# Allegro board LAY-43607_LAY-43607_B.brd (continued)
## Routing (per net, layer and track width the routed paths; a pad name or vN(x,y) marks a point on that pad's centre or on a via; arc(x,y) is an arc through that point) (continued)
D1_MDQ31: length 46.4
  TOP w0.137: v2(80.79,18.2) 80.79,18.64 81.01,18.86 81.62,18.86 81.81,18.67 81.81,18.32 81.67,18.18 81.59,18.18 81.46,18.04 81.46,17.77 81.59,17.63 81.67,17.63 81.81,17.5 81.81,16.86 U16.D7 ; v3(67.83,36.59) 67.42,36.99 U14.L25
  BOTTOM w0.137: v2(80.79,18.2) 80,18.2 78.44,19.75 76.47,19.75 75.82,19.1 75.82,15.79 75.65,15.62 74.9,15.62 74.76,15.76 74.76,16.53 74.9,16.67 75.22,16.67 75.36,16.8 75.36,17.08 75.22,17.22 74.9,17.22 74.76,17.35 74.76,17.63 74.9,17.76 75.22,17.76 75.36,17.9 75.36,18.18 75.22,18.31 74.9,18.31 74.76,18.45 74.76,18.72 74.9,18.86 75.22,18.86 75.36,19 75.36,19.27 75.22,19.41 74.9,19.41 74.76,19.55 74.76,19.89 74.14,20.5 72.34,20.5 72.34,20.5 70.44,20.5 69.93,21.01 69.93,27.33 67.22,30.04 67.22,31.82 66.46,32.59 66.46,35.47 66.62,35.63 66.62,35.97 66.86,36.21 67.22,36.21 67.6,36.59 v3(67.83,36.59)
D1_MDQ32: length 47
  TOP w0.137: U17.G2 56.4,12.91 58.2,12.91 v2(58.2,12.9) ; U14.V24 v3(61.42,37.4)
  BOTTOM w0.137: v3(61.42,37.4) 61.85,36.97 61.85,35.16 61.68,34.99 61.68,33.28 62.06,32.9 62.06,31.26 61.96,31.16 61.96,29.69 62.41,29.23 62.41,29.04 62.12,28.75 62.12,28.56 62.32,28.36 62.51,28.36 62.8,28.65 63,28.65 63.23,28.42 63.23,27.98 63.09,27.84 62.41,27.84 62.27,27.71 62.27,27.43 62.41,27.3 63.09,27.3 63.23,27.16 63.23,26.72 63.44,26.52 63.44,26.32 63.05,25.94 63.05,25.74 63.24,25.55 63.43,25.55 63.71,25.82 64.08,25.82 64.22,25.69 64.22,24.97 64.08,24.84 63.4,24.84 63.26,24.7 63.26,24.42 63.4,24.29 64.08,24.29 64.22,24.15 64.22,23.88 64.08,23.74 63.4,23.74 63.26,23.6 63.26,23.33 63.4,23.19 64.08,23.19 64.22,23.05 64.22,22.53 64.55,22.2 65.25,22.2 65.48,21.97 65.48,20.91 65.63,20.76 66.16,20.76 66.34,20.58 66.34,20.39 66.15,20.2 64.81,20.2 64.58,19.96 64.35,19.96 63.88,20.43 63.65,20.43 63.49,20.27 63.49,20.04 63.96,19.58 63.96,19.35 63.77,19.16 63.12,19.16 62.5,18.54 62.5,17.23 63.23,16.5 63.23,16.27 62.84,15.88 62.55,15.88 62.42,16.02 62.42,16.26 62.17,16.51 61,16.51 60.8,16.31 60.8,15.14 60.57,14.91 60.24,14.91 60,14.67 60,14.26 59.65,13.91 59.18,13.91 59,13.73 59,13.39 58.51,12.9 v2(58.2,12.9)
D1_MDQ33: length 47.1
  TOP w0.137: v3(62.22,35.79) 62.22,35.8 U14.U26 ; U17.F7 v2(60.4,14.51)
  BOTTOM w0.137: v2(60.4,14.51) 60.8,14.11 61.69,14.11 61.85,14.27 61.85,14.75 61.99,14.89 62.26,14.89 62.4,14.75 62.4,14.27 62.62,14.05 63.06,14.05 63.26,14.25 63.26,14.67 63.12,14.8 63.12,15.54 63.67,16.09 64.01,16.09 64.37,16.45 64.37,16.9 64.21,17.06 63.29,17.06 63.13,17.22 63.13,17.45 63.29,17.61 64.21,17.61 64.37,17.77 64.37,18 64.21,18.16 63.29,18.16 63.13,18.32 63.13,18.55 63.29,18.71 64.21,18.71 64.37,18.87 64.37,19.13 64.99,19.75 66.64,19.75 66.88,20 66.88,21.08 66.76,21.21 66.2,21.21 65.92,21.49 65.92,22.01 65.97,22.06 65.97,22.5 65.84,22.64 65.15,22.64 65.01,22.78 65.01,23.05 65.15,23.19 65.84,23.19 65.97,23.33 65.97,23.6 65.84,23.74 65.15,23.74 65.01,23.88 65.01,24.15 65.15,24.29 65.84,24.29 65.97,24.42 65.97,24.7 65.84,24.84 65.15,24.84 65.01,24.97 65.01,25.25 65.15,25.39 65.84,25.39 65.97,25.52 65.97,25.96 65.55,26.39 65.35,26.39 64.87,25.9 64.68,25.9 64.48,26.1 64.48,26.29 64.97,26.77 64.97,26.97 64.77,27.16 64.58,27.16 64.09,26.68 63.9,26.68 63.7,26.87 63.7,27.07 64.19,27.55 64.19,27.74 63.76,28.17 63.76,29.06 63.09,29.74 62.54,29.74 62.4,29.87 62.4,30.77 62.93,31.31 62.93,32.25 62.8,32.38 62.64,32.38 62.5,32.52 62.5,32.93 62.64,33.07 63.2,33.07 63.33,33.2 63.33,33.48 63.2,33.62 62.89,33.62 62.67,33.83 62.67,34.03 62.81,34.16 63.2,34.16 63.33,34.3 63.33,34.69 v3(62.22,35.79)
D1_MDQ34: length 47
  TOP w0.137: v3(59.02,35.79) 59.42,36.19 U14.AA26 ; U17.H3 v2(57.37,12.51)
  BOTTOM w0.137: v3(59.02,35.79) 59.02,35.64 58.53,35.15 58.53,33.71 58.49,33.67 58.49,33.4 57.94,32.86 57.94,27.95 57.84,27.85 57.84,26.87 57.71,26.73 57.53,26.73 57.33,26.93 57.33,27.4 57.19,27.53 57.02,27.53 56.82,27.34 56.82,26.76 56.74,26.68 56.61,26.68 56.43,26.5 56.43,26.27 56.57,26.13 56.98,26.13 57.15,25.97 57.15,25.74 56.98,25.58 56.61,25.58 56.45,25.42 56.45,25.19 56.61,25.03 56.98,25.03 57.15,24.87 57.15,22.46 57.66,21.95 57.66,21.72 57.5,21.56 57.31,21.56 57.15,21.4 57.15,21.09 57.31,20.93 57.5,20.93 57.64,20.79 57.64,20.6 57.5,20.46 57.17,20.46 57.05,20.34 57.05,20.19 57.16,20.07 57.95,20.07 58.15,19.87 58.15,19.42 57.89,19.16 57.29,19.16 57.08,18.95 57.08,18.49 57.28,18.28 58.12,18.28 58.29,18.11 58.29,17.57 58.2,17.48 57.8,17.48 57.21,16.89 57.21,16.74 57.39,16.56 57.58,16.56 57.93,16.91 58.65,16.91 58.83,16.73 58.83,16.28 58.66,16.11 57.94,16.11 57.85,16.19 57.35,16.19 57.19,16.03 57.19,15.18 57.66,14.7 57.66,14.4 57.9,14.17 58.45,14.17 58.59,14.03 58.59,13.63 58.45,13.49 57.78,13.49 57.72,13.42 57.72,13.27 57.58,13.13 57.26,13.13 57.16,13.23 57.16,14.35 56.98,14.53 56.61,14.53 56.44,14.36 56.44,13.27 56.28,13.11 56.05,13.11 55.89,13.27 55.89,13.95 55.73,14.11 55.44,14.11 55.31,13.97 55.31,13 55.55,12.75 57.13,12.75 v2(57.37,12.51)
D1_MDQ35: length 47
  TOP w0.137: U17.H7 59.6,12.91 59.18,12.91 58.92,13.17 58.92,14.94 59.09,15.12 59.41,15.12 59.6,15.32 59.6,15.63 59.5,15.73 59.09,15.73 58.92,15.91 58.92,17 58.05,17.87 58.05,18.06 58.29,18.3 58.29,18.5 58.1,18.69 57.9,18.69 57.49,18.28 57.29,18.28 57.07,18.51 56.89,18.51 55.99,19.41 55.66,19.41 55.49,19.58 55.49,20.23 55.78,20.52 58.97,20.52 59.51,19.97 59.51,19.67 59.4,19.56 59.16,19.56 58.61,20.11 56.25,20.11 56.12,19.97 56.12,19.78 56.75,19.14 58.21,19.14 v2(58.65,18.7) ; U14.W23 61.02,38.59 v3(60.62,38.19)
  BOTTOM w0.137: v3(60.62,38.19) 60.25,37.82 60.25,36.44 60.01,36.2 59.66,36.2 59.43,35.96 59.43,35.63 59.48,35.58 59.48,33.13 59.34,32.99 58.76,32.99 58.38,32.62 58.38,29.31 58.77,28.92 58.77,28.53 58.38,28.14 58.38,27.77 58.29,27.67 58.29,26.57 58,26.29 57.76,26.29 57.59,26.12 57.59,25.04 57.92,24.72 57.92,24.48 57.59,24.15 57.59,23.03 57.59,23.02 57.59,22.97 58.1,22.45 58.1,20.94 58.59,20.46 58.59,19.14 58.65,19.08 v2(58.65,18.7)
D1_MDQ36: length 47
  TOP w0.137: v2(58.71,12.26) 57.97,12.26 57.81,12.11 56.55,12.11 56.15,12.51 U17.H2 ; v3(62.22,37.39) 62.62,37.79 U14.U24
  BOTTOM w0.137: v2(58.71,12.26) 58.95,12.5 59.47,12.5 59.63,12.66 59.63,12.91 59.79,13.07 60.02,13.07 60.18,12.91 60.18,12.66 60.34,12.5 63.71,12.5 64.34,13.13 64.34,14.32 64.71,14.69 65.25,14.69 65.41,14.85 65.41,15.49 65.88,15.96 65.88,16.37 66.02,16.51 67.25,16.51 67.48,16.27 67.48,15.73 67.78,15.43 69.05,15.43 69.36,15.74 69.36,16.34 69.2,16.5 68.07,16.5 67.9,16.67 67.9,16.9 68.05,17.05 69.2,17.05 69.36,17.21 69.36,18.95 67.8,20.51 67.8,20.68 67.77,20.72 67.77,26.58 65.46,28.89 65.46,29.3 65.45,29.31 65.45,30.95 64.12,32.29 64.12,35.53 64.22,35.63 64.22,35.96 64.12,36.06 64.12,36.36 64.2,36.44 64.2,36.75 63.97,36.97 62.64,36.97 v3(62.22,37.39)
D1_MDQ37: length 47
  TOP w0.137: U17.H8 v2(61.2,12.91) ; U14.U25 62.22,36.6 v3(62.22,36.59)
  BOTTOM w0.137: v2(61.2,12.91) 61.6,13.31 62.82,13.31 63.12,13.61 63.42,13.61 63.73,13.92 63.73,14.82 63.57,14.98 63.57,15.36 63.83,15.62 63.84,15.62 63.87,15.65 64.64,15.65 64.81,15.82 64.81,18.95 65.18,19.31 65.58,19.31 65.59,19.31 67.25,19.31 67.48,19.08 67.48,18.38 67.62,18.24 68.55,18.24 68.73,18.43 68.73,18.86 67.36,20.24 67.36,20.5 67.33,20.53 67.33,21.62 67.19,21.76 66.64,21.76 66.5,21.9 66.5,22.17 66.64,22.31 67.19,22.31 67.33,22.45 67.33,22.72 67.19,22.86 66.64,22.86 66.5,23 66.5,23.27 66.64,23.41 67.19,23.41 67.33,23.54 67.33,23.82 67.19,23.96 66.64,23.96 66.5,24.09 66.5,24.37 66.64,24.5 67.19,24.5 67.33,24.64 67.33,24.92 67.19,25.05 66.64,25.05 66.5,25.19 66.5,25.47 66.64,25.6 67.19,25.6 67.33,25.74 67.33,26.4 66.85,26.88 66.65,26.88 66.26,26.49 66.07,26.49 65.88,26.68 65.88,26.88 66.27,27.26 66.27,27.46 66.07,27.65 65.88,27.65 65.49,27.26 65.3,27.26 65.1,27.46 65.1,27.65 65.49,28.04 65.49,28.23 65.29,28.43 65.1,28.43 64.71,28.04 64.52,28.04 64.32,28.24 64.32,28.43 64.71,28.82 64.71,29.01 64.23,29.49 64.23,30.08 64.1,30.22 63.51,30.22 63.37,30.36 63.37,30.64 63.51,30.77 64.06,30.77 64.23,30.95 64.23,31.22 63.68,31.77 63.68,35.04 63.43,35.29 63.43,35.97 63.21,36.2 62.62,36.2 v3(62.22,36.59)
D1_MDQ38: length 47
  TOP w0.137: v3(60.62,37.4) U14.W24 ; U17.J3 57.99,11.71 v2(58.08,11.79)
  BOTTOM w0.137: v2(58.08,11.79) 57.83,11.55 57.83,10.58 58.03,10.38 58.46,10.38 59.17,11.09 59.43,11.09 59.66,11.32 59.66,11.69 60.08,12.11 62.71,12.11 62.95,11.87 63.75,11.87 64.49,12.61 65.57,12.61 65.85,12.9 65.85,14.7 66.07,14.91 68.11,14.91 68.27,15.07 69.43,15.07 69.61,15.25 69.61,19.41 68.24,20.78 68.24,20.87 68.21,20.9 68.21,26.76 65.9,29.07 65.9,29.48 65.89,29.49 65.89,31.14 64.6,32.43 64.6,37.25 64.09,37.77 61,37.77 v3(60.62,37.4)
D1_MDQ39: length 47
  TOP w0.137: v2(57.56,17.88) 58.56,16.88 58.56,13.15 U17.J7 ; v3(59.82,36.59) 60.22,36.99 U14.Y25
  BOTTOM w0.137: v3(59.82,36.59) 59.62,36.59 59.24,36.21 58.8,36.21 58.66,36.08 58.66,35.96 58.65,35.95 58.65,35.8 58.62,35.77 58.62,35.63 58.39,35.4 58.26,35.4 58.13,35.26 58.13,34.08 57.81,33.77 57.81,33.32 57.49,32.99 57.49,28.63 55.99,27.13 55.99,24.71 56.36,24.34 56.54,24.34 56.7,24.18 56.7,23.95 56.54,23.79 56.36,23.79 56.2,23.63 56.2,23.4 56.36,23.24 56.54,23.24 56.7,23.08 56.7,22.86 56.54,22.69 56.36,22.69 56.2,22.53 56.2,22.31 56.36,22.15 56.54,22.15 56.7,21.99 56.7,21.76 56.54,21.6 56.36,21.6 56.2,21.44 56.2,21.21 56.36,21.05 56.54,21.05 56.7,20.89 56.7,20.66 56.54,20.5 55.79,20.5 55.65,20.36 55.65,20.16 55.86,19.95 56.54,19.95 56.7,19.79 56.7,19.56 56.54,19.4 55.79,19.4 55.65,19.27 55.65,19.06 55.86,18.85 56.54,18.85 56.7,18.69 56.7,18.09 56.82,17.97 56.82,17.44 56.62,17.24 56.11,17.24 56,17.13 56,15.94 55.77,15.71 54.58,15.71 54.58,15.71 54.51,15.71 54.35,15.54 53.44,15.54 53.24,15.34 53.24,15.06 53.39,14.91 55.77,14.91 55.77,14.9 56.6,14.9 56.86,15.16 56.86,17 57.24,17.38 57.24,17.56 v2(57.56,17.88)
D1_MDQ40: length 46.9
  TOP w0.137: v2(59.95,19.22) 59.95,20.22 59.21,20.96 55.6,20.96 55.05,20.41 55.05,19.3 55.2,19.14 55.77,19.14 U17.A3 ; U14.AB24 58.63,37.8 v3(59.02,38.19)
  L4_INT_2 w0.107: v3(59.02,38.19) 58.67,37.84 58,37.84 57.78,37.62 57.78,37.24 57.52,36.97 57.26,36.97 57.01,36.72 57.01,35.96 57.01,35.96 57.01,35.41 56.88,35.29 56.47,35.29 56.31,35.13 56.31,34.98 56.43,34.86 56.99,34.86 57.13,34.72 57.13,34.57 56.99,34.43 56.62,34.43 56.5,34.31 56.5,34.13 56.62,34.01 56.83,34.01 56.94,33.9 56.94,33.26 56.32,32.63 56.32,32.48 56.43,32.38 57.02,32.38 57.07,32.33 57.07,32 57.02,31.95 56.39,31.95 56.27,31.82 56.27,25.1 55.67,24.51 55.67,24.33 56.05,23.96 56.05,23.79 55.92,23.66 55.73,23.66 55.37,24.03 55.19,24.03 55.03,23.86 55.03,21.45 55.19,21.29 55.57,21.29 55.69,21.41 55.69,22.91 55.8,23.02 55.95,23.02 56.12,22.85 56.12,21.4 56.24,21.27 56.42,21.27 56.55,21.4 56.55,22.53 56.67,22.65 56.85,22.65 56.97,22.53 56.97,21.41 57.1,21.29 57.4,21.29 57.53,21.41 57.53,21.82 57.68,21.97 57.84,21.97 57.95,21.86 57.95,21.41 58.08,21.29 58.42,21.29 59.4,20.31 59.4,19.39 59.57,19.22 v2(59.95,19.22)
D1_MDQ41: length 46.9
  TOP w0.137: U17.B8 60.42,16.93 60.42,16.92 v2(60.4,16.91) ; v3(58.22,36.59) 58.62,36.99 U14.AB25
  L4_INT_2 w0.107: v2(60.4,16.91) 59.83,16.91 59.04,16.12 57.76,16.12 55.53,13.9 55.53,12.59 55.76,12.36 56.12,12.36 56.37,12.62 56.37,13.42 57.9,14.95 58.53,14.95 60.07,16.49 61.04,16.49 61.21,16.49 61.62,16.9 61.62,18.65 62.06,19.09 62.06,19.56 61.93,19.69 61.39,19.69 61.27,19.81 61.27,19.99 61.39,20.11 61.93,20.11 62.06,20.24 62.06,20.41 61.93,20.54 61.39,20.54 61.27,20.66 61.27,20.84 61.39,20.97 61.93,20.97 62.06,21.09 62.06,21.27 61.93,21.39 61.39,21.39 61.27,21.52 61.27,21.7 61.39,21.82 61.93,21.82 62.06,21.95 62.06,23.82 60.28,25.6 60.28,30.05 60.28,30.05 60.28,30.2 59.5,30.98 59.5,31.33 59.37,31.46 58.54,31.46 58.42,31.58 58.42,31.76 58.54,31.88 59.37,31.88 59.5,32.01 59.5,32.19 59.37,32.31 58.54,32.31 58.42,32.44 58.42,32.61 58.54,32.74 59.37,32.74 59.5,32.86 59.5,33.92 59.39,34.03 59.18,34.03 59.07,34.14 59.07,34.35 59.18,34.46 59.39,34.46 59.5,34.56 59.5,35.12 59.18,35.44 58.88,35.44 58.61,35.7 58.61,36.21 v3(58.22,36.59)
D1_MDQ42: length 46.9
  TOP w0.137: U14.AE25 56.22,36.99 v3(56.62,36.59) ; v2(58.1,16.51) 58.1,15.97 57.55,15.42 57.35,15.42 57.22,15.56 57.22,16.17 57.54,16.49 57.54,16.78 57.4,16.91 57.21,16.91 U17.C3
  L4_INT_2 w0.107: v2(58.1,16.51) 59.02,16.51 59.28,16.77 59.28,16.94 58.85,17.38 58.85,17.54 58.99,17.69 59.14,17.69 59.58,17.25 59.89,17.25 60.02,17.38 60.02,17.83 59.93,17.92 59.42,17.92 59.29,18.04 59.29,18.22 59.42,18.34 59.8,18.34 59.93,18.47 59.93,18.7 59.7,18.94 59.27,18.94 58.99,19.22 58.99,20.03 58.14,20.88 57.02,20.88 56.16,20.02 56.16,19.34 55.99,19.17 55.84,19.17 55.76,19.25 55.76,19.82 55.61,19.96 55.46,19.96 55.33,19.83 55.33,19.26 55.23,19.17 55.05,19.17 54.95,19.27 54.95,19.63 54.51,20.07 54.51,20.22 54.62,20.33 55.94,20.33 56.04,20.43 56.04,20.63 55.92,20.75 54.74,20.75 54.62,20.88 54.62,24.21 55.08,24.67 55.25,24.67 55.86,25.28 55.86,29.23 55.76,29.33 55.53,29.33 55.43,29.42 55.43,29.57 55.51,29.65 55.76,29.65 55.86,29.74 55.86,29.87 55.76,29.97 55.51,29.97 55.43,30.05 55.43,30.21 55.51,30.29 55.76,30.29 55.86,30.38 55.86,30.51 55.76,30.61 55.51,30.61 55.43,30.69 55.43,30.85 55.51,30.93 55.76,30.93 55.86,31.02 55.86,31.15 55.76,31.25 55.51,31.25 55.43,31.33 55.43,31.49 55.51,31.57 55.76,31.57 55.86,31.66 55.86,31.79 55.76,31.89 55.63,31.89 55.53,31.99 55.53,32.09 55.65,32.21 55.76,32.21 55.86,32.3 55.86,32.43 55.72,32.57 55.72,32.72 56.31,33.32 56.31,34.01 56.12,34.21 55.46,34.21 55.15,34.52 55.15,34.65 55.3,34.8 55.3,34.94 55.2,35.03 55.07,35.03 54.92,34.88 54.79,34.88 54.62,35.04 54.62,35.29 54.73,35.4 56.02,35.4 56.18,35.56 56.18,36.15 v3(56.62,36.59)
D1_MDQ43: length 46.7
  TOP w0.137: U17.C7 59.53,16.98 59.53,18.57 58.45,19.64 v2(57.63,19.64) ; U14.AF25 55.43,37 v3(55.82,37.39)
  L4_INT_2 w0.107: v3(55.82,37.39) 54.89,37.39 54.51,37.01 53.67,37.01 53.23,37.45 51.57,37.45 51.25,37.13 51.25,34.01 51.57,33.69 52.8,33.69 53.02,33.91 53.52,33.91 53.81,33.62 53.81,33.32 54.1,33.03 54.1,32.65 54.1,32.65 54.1,25.46 52.85,24.21 52.85,17.05 52.59,16.79 52.59,15.57 52.7,15.46 52.78,15.38 52.78,14.81 52.55,14.58 52.55,14.03 52.9,13.68 53.41,13.68 53.66,13.93 53.66,14.49 53.66,14.49 53.66,16.23 53.95,16.52 54.99,16.52 55.22,16.75 55.22,17.1 55.43,17.31 56.55,17.31 56.78,17.55 56.78,17.73 57.63,18.57 v2(57.63,19.64)
D1_MDQ44: length 46.8
  TOP w0.137: v3(59.82,37.39) 59.82,37.4 U14.Y24 ; v2(55.6,16.91) U17.C2
  L4_INT_2 w0.107: v3(59.82,37.39) 60.21,37.01 60.21,33.21 61.12,32.3 61.12,25.95 62.88,24.19 62.88,16.58 62.48,16.18 62.48,12.29 62.34,12.15 59.98,12.15 59.7,11.87 59.1,11.87 58.88,11.65 58.88,11.29 58.5,10.91 57.34,10.91 56.96,11.29 56.6,11.29 56.38,11.51 56.38,11.87 56.16,12.09 54.25,12.09 53.67,11.51 52.86,11.51 52.65,11.72 52.65,11.99 52.79,12.13 53.48,12.13 54.42,13.06 54.42,13.07 54.64,13.29 54.96,13.29 55.2,13.54 55.2,14.69 55.44,14.92 55.76,14.92 55.98,15.15 55.98,16.52 v2(55.6,16.91)
D1_MDQ45: length 46.8
  TOP w0.137: U14.AA25 59.42,37 v3(59.02,37.39) ; U17.C8 v2(60.4,16.11)
  L4_INT_2 w0.107: v2(60.4,16.11) 60.67,15.84 60.67,15.8 60.78,15.68 60.78,15.05 60.62,14.89 59.06,14.89 57.52,13.35 56.93,13.35 56.68,13.1 56.68,11.98 57.45,11.21 58.22,11.21 58.51,11.5 58.51,11.92 58.29,12.14 58.29,12.39 58.55,12.65 58.94,12.65 59.33,12.26 59.54,12.26 59.73,12.45 59.73,12.6 59.03,13.3 59.03,13.75 59.37,14.09 60.36,14.09 60.78,13.67 60.78,12.63 60.89,12.52 61.44,12.52 61.58,12.67 61.58,14.23 61.71,14.36 62.14,14.36 62.26,14.48 62.26,14.66 62.14,14.78 61.71,14.78 61.58,14.91 61.58,16.23 61.84,16.49 62.13,16.49 62.47,16.83 62.47,24.02 60.69,25.8 60.69,31.84 59.99,32.55 59.99,35.09 59.4,35.68 59.4,37.02 v3(59.02,37.39)
D1_MDQ46: length 46.7
  TOP w0.137: U14.AD25 57.03,37 v3(57.42,37.39) ; U17.D3 v2(56.4,16.11)
  L4_INT_2 w0.107: v3(57.42,37.39) 57.37,37.39 56.95,36.98 55.11,36.98 54.87,36.75 53.58,36.75 53.28,37.04 51.93,37.04 51.66,36.77 51.66,34.53 51.9,34.29 54.06,34.29 54.62,33.73 54.62,33.32 54.62,33.32 54.62,32.18 54.61,32.17 54.61,28.66 54.74,28.54 54.9,28.54 55.03,28.41 55.03,28.23 54.9,28.11 54.74,28.11 54.61,27.98 54.61,27.81 54.74,27.68 54.9,27.68 55.03,27.56 55.03,27.38 54.9,27.26 54.74,27.26 54.61,27.13 54.61,26.95 54.74,26.83 54.9,26.83 55.03,26.7 55.03,26.53 54.9,26.4 54.74,26.4 54.61,26.28 54.61,26.04 54.74,25.92 54.91,25.92 55.03,25.79 55.03,25.62 54.91,25.49 54.74,25.49 53.26,24.02 53.26,16.97 53.4,16.84 53.68,16.84 53.78,16.94 54.29,16.94 54.68,17.32 54.96,17.32 55.18,17.55 55.18,17.87 55.44,18.12 56.52,18.12 56.98,18.58 56.98,19.67 57.36,20.06 57.8,20.06 58.1,19.75 58.1,19.21 58.25,19.06 58.25,18.82 58.13,18.7 57.98,18.7 57.85,18.57 57.85,18.4 57.98,18.27 58.13,18.27 58.25,18.15 58.25,17.2 57.8,16.75 57.63,16.75 57.19,17.19 57.02,17.19 56.9,17.07 56.9,16.88 57.33,16.45 57.33,16.22 56.99,15.88 56.63,15.88 v2(56.4,16.11)
D1_MDQ47: length 46.7
  TOP w0.137: U17.D7 59.24,16.47 59.24,17.42 v2(58.69,17.97) ; v3(55.82,35.8) U14.AE26
  L4_INT_2 w0.107: v2(58.69,17.97) 59.03,18.32 59.03,18.86 58.51,19.38 58.51,19.92 57.97,20.47 57.19,20.47 56.57,19.85 56.57,19.19 56.27,18.89 55.44,18.89 55.22,18.67 55.22,18.21 55.1,18.09 54.64,18.09 54.27,17.72 53.96,17.72 53.67,18 53.67,18.39 53.8,18.52 54.16,18.52 54.28,18.63 54.28,18.81 54.14,18.94 53.8,18.94 53.67,19.07 53.67,19.25 53.8,19.37 53.96,19.37 54.08,19.5 54.08,19.67 53.96,19.8 53.8,19.8 53.67,19.92 53.67,20.29 53.8,20.42 53.97,20.42 54.1,20.54 54.1,20.72 53.97,20.85 53.8,20.85 53.67,20.97 53.67,21.15 53.8,21.27 53.97,21.27 54.1,21.4 54.1,21.57 53.97,21.7 53.8,21.7 53.67,21.82 53.67,22 53.8,22.13 53.97,22.13 54.1,22.25 54.1,22.43 53.97,22.55 53.8,22.55 53.67,22.68 53.67,22.85 53.8,22.98 53.97,22.98 54.1,23.1 54.1,23.28 53.97,23.41 53.8,23.41 53.67,23.53 53.67,23.85 54.91,25.08 55.08,25.08 55.45,25.45 55.45,25.96 55.44,25.97 55.44,28.83 55.02,29.25 55.02,32 55.03,32 55.03,32.18 55.25,32.4 55.25,33.98 54.65,34.59 53.1,34.59 52.99,34.7 52.27,34.7 52.11,34.86 52.11,35.35 52.24,35.48 54.2,35.48 54.32,35.59 54.32,35.77 54.19,35.9 52.24,35.9 52.11,36.03 52.11,36.4 52.34,36.63 53.38,36.63 53.65,36.36 55.25,36.36 v3(55.82,35.8)
D1_MDQ48: length 47.6
  TOP w0.137: v3(59.02,38.99) 59.42,39.39 U14.AA22 ; U18.G2 44.92,13.71 44.92,14.27 45.16,14.51 45.71,14.51 45.91,14.71 47.67,14.71 v2(48.02,14.36)
  BOTTOM w0.137: v3(59.02,38.99) 58.62,38.59 58.62,37.23 58.36,36.97 58.07,36.97 57.8,36.69 57.8,36.44 57.57,36.21 57.26,36.21 57.02,35.97 57.02,35.63 56.36,34.97 56.36,32.28 56.26,32.18 56.26,29.03 55,27.77 55,24.15 54.38,23.53 54.38,23.3 55,22.68 55,22.37 54.87,22.24 54.67,22.24 53.99,22.91 53.76,22.91 53.6,22.75 53.6,22.52 54.25,21.87 54.25,21.62 54.09,21.46 53.89,21.46 53.22,22.13 52.99,22.13 52.83,21.97 52.83,21.75 53.48,21.1 53.48,20.84 53.32,20.68 53.11,20.68 52.44,21.36 52.21,21.36 51.06,20.21 51.06,17.84 51.23,17.68 51.62,17.68 51.78,17.52 51.78,17.29 51.62,17.13 51.23,17.13 51.06,16.97 51.06,16.74 51.23,16.58 51.62,16.58 51.78,16.42 51.78,16.19 51.62,16.03 51.23,16.03 51.06,15.87 51.06,14.54 50.63,14.11 50.26,14.11 50.12,13.97 50.12,12.67 49.98,12.53 49.45,12.53 49.32,12.66 49.32,13.07 49.09,13.31 48.66,13.31 48.3,13.66 48.3,14.08 v2(48.02,14.36)
D1_MDQ49: length 47.6
  TOP w0.137: U18.F7 v2(48.92,14.51) ; v3(58.22,38.19) 58.62,38.59 U14.AB23
  BOTTOM w0.137: v3(58.22,38.19) 58.22,37.96 57.82,37.56 57.82,37.27 57.58,37.02 57.31,37.02 57.01,36.72 57.01,36.45 56.78,36.22 56.48,36.22 56.23,35.96 56.23,35.67 55.98,35.42 55.44,35.42 55.22,35.2 55.22,34.46 55.08,34.33 54.79,34.33 54.66,34.19 54.66,33.92 54.82,33.76 55.23,33.76 55.39,33.59 55.39,33.37 55.23,33.21 54.74,33.21 54.58,33.05 54.58,32.82 54.75,32.66 55.62,32.66 55.77,32.51 55.77,32.28 55.6,32.11 54.82,32.11 54.66,31.95 54.66,31.72 54.82,31.56 55.62,31.56 55.77,31.41 55.77,31.18 55.6,31.01 54.91,31.01 54.74,30.84 54.74,30.11 54.97,29.88 55.68,29.88 55.82,29.74 55.82,29.47 55.68,29.33 55.36,29.33 55.22,29.19 55.22,28.62 54.39,27.79 54.39,26.15 53.75,25.52 53.75,25.32 54.41,24.66 54.41,24.47 54.22,24.27 54.03,24.27 53.26,25.04 53.07,25.04 52.87,24.84 52.87,24.65 53.73,23.79 53.73,23.6 53.54,23.4 53.34,23.4 52.49,24.26 52.29,24.26 52.1,24.07 52.1,23.87 52.95,23.02 52.95,22.82 52.76,22.63 52.57,22.63 51.71,23.48 51.52,23.48 51.32,23.29 51.32,23.1 52.18,22.24 52.18,22.05 51.98,21.85 51.79,21.85 51.04,22.61 50.84,22.61 50.62,22.38 50.62,22.05 50.49,21.92 49.86,21.92 49.7,21.75 49.7,21.5 49.83,21.37 50.49,21.37 50.62,21.23 50.62,19.69 50.08,19.15 49.78,19.15 49.24,18.61 49.24,15.49 48.92,15.17 v2(48.92,14.51)
D1_MDQ50: length 47.7
  TOP w0.137: v3(58.22,39.8) 57.82,39.4 U14.AC22 ; U18.H3 v2(44.92,12.91)
  BOTTOM w0.137: v2(44.92,12.91) 42.54,12.91 42.3,13.15 42.3,13.51 41.79,14.02 41.79,14.66 41.95,14.82 42.37,14.82 42.53,14.98 42.53,15.21 42.37,15.37 41.95,15.37 41.79,15.53 41.79,25.71 43.62,27.53 43.62,29.02 43.17,29.47 42.9,29.47 42.76,29.61 42.76,30.12 42.9,30.26 43.49,30.26 44.23,31 44.23,32.19 44.56,32.53 44.56,32.76 44.04,33.28 44.04,33.51 44.2,33.67 44.43,33.67 44.95,33.14 45.18,33.14 45.34,33.3 45.34,33.53 44.82,34.05 44.82,34.28 44.98,34.44 45.2,34.44 45.73,33.92 45.95,33.92 46.5,34.47 46.5,34.99 46.75,35.24 47.27,35.24 51.83,39.8 54.46,39.8 54.86,40.19 56.79,40.19 57.19,39.8 v3(58.22,39.8)
D1_MDQ51: length 47.7
  TOP w0.137: U14.AB22 58.62,39.39 v3(58.22,38.99) ; U18.H7 v2(48.12,12.91)
  BOTTOM w0.137: v3(58.22,38.99) 57.85,38.62 57.85,38.09 57.58,37.82 57.32,37.82 57.02,37.52 57.02,37.23 56.79,37 56.4,37 56.25,36.85 56.25,36.46 55.99,36.2 55.37,36.2 55.21,36.36 55.21,36.49 55.08,36.63 54.8,36.63 54.66,36.49 54.66,36.33 54.53,36.2 54.18,36.2 53.83,35.85 53.83,34.83 53.76,34.77 53.76,33.18 53.91,33.03 53.91,32.48 53.75,32.32 53.5,32.32 53.34,32.16 53.34,31.94 53.5,31.77 53.75,31.77 53.91,31.61 53.91,31.35 53.77,31.21 53.5,31.21 53.36,31.08 53.36,30.8 53.5,30.66 54.16,30.66 54.29,30.53 54.29,30.25 54.16,30.12 53.47,30.12 53.34,29.98 53.34,29.7 53.47,29.57 54.57,29.57 54.71,29.43 54.71,29.16 54.57,29.02 53.47,29.02 53.34,28.88 53.34,28.61 53.47,28.47 53.77,28.47 53.91,28.33 53.91,27.68 53.33,27.11 53.33,26.91 53.67,26.58 53.67,26.35 53.06,25.74 52.84,25.74 52.53,26.05 52.3,26.05 52.14,25.88 52.14,25.66 52.45,25.35 52.45,25.13 52.29,24.96 52.06,24.96 51.76,25.27 51.53,25.27 51.37,25.11 51.37,24.88 51.67,24.58 51.67,24.35 51.51,24.19 51.28,24.19 50.98,24.49 50.75,24.49 50.59,24.33 50.59,24.1 50.9,23.8 50.9,23.57 50.73,23.41 50.51,23.41 50.2,23.72 49.98,23.72 49.81,23.56 49.81,23.33 50.12,23.02 50.12,22.8 49.96,22.64 49.73,22.64 49.43,22.94 49.2,22.94 49.04,22.78 49.04,22.55 49.34,22.25 49.34,22.02 48.81,21.49 48.81,21.01 48.97,20.85 49.96,20.85 50.12,20.69 50.12,20.47 49.96,20.31 48.97,20.31 48.81,20.14 48.81,15.73 47.61,14.53 47.61,14 47.84,13.77 47.84,13.19 v2(48.12,12.91)
D1_MDQ52: length 47.7
  TOP w0.137: v2(46.7,12.82) 46.3,12.82 45.58,12.11 45.09,12.11 44.69,12.51 U18.H2 ; v3(60.62,39.8) 60.22,39.4 U14.Y22
  BOTTOM w0.137: v3(60.62,39.8) 60.49,39.8 60.08,39.39 57.26,39.39 57.05,39.18 57.05,38.89 56.78,38.62 53.62,38.62 50.48,35.48 50.48,33.64 48.07,31.22 48.07,27.43 45.2,24.57 43.67,24.57 43.29,24.18 43.29,23.78 43.45,23.62 44.29,23.62 44.46,23.46 44.46,23.23 44.29,23.07 43.45,23.07 43.29,22.91 43.29,22.68 43.45,22.52 44.29,22.52 44.46,22.36 44.46,22.13 44.29,21.97 43.45,21.97 43.29,21.81 43.29,20.78 43.97,20.09 44.86,20.09 45.87,19.08 45.87,13.6 46.65,12.82 v2(46.7,12.82)
D1_MDQ53: length 47.7
  TOP w0.137: U14.AA23 59.43,38.6 v3(59.82,38.99) ; U18.H8 v2(48.92,12.91)
  BOTTOM w0.137: v2(48.92,12.91) 48.92,12.41 49.13,12.21 51.12,12.21 51.24,12.34 51.58,12.34 51.86,12.61 51.86,12.74 52.02,12.9 52.55,12.9 52.72,13.06 52.72,13.29 52.55,13.45 52.02,13.45 51.86,13.61 51.86,13.84 52.02,14 52.52,14 52.66,14.13 52.66,14.52 52.48,14.69 52.02,14.69 51.85,14.86 51.85,15.42 52.22,15.79 52.22,15.87 52.38,16.03 53.08,16.03 53.24,16.19 53.24,16.42 53.08,16.58 52.38,16.58 52.22,16.74 52.22,16.97 52.38,17.13 53.08,17.13 53.24,17.29 53.24,17.52 53.08,17.68 52.38,17.68 52.22,17.84 52.22,18.1 52.08,18.24 51.72,18.24 51.58,18.39 51.58,18.71 51.69,18.83 53.14,18.83 53.27,18.96 53.27,19.24 53.12,19.4 51.71,19.4 51.58,19.53 51.58,19.86 51.87,20.16 53.52,20.16 53.86,20.51 54.09,20.51 54.3,20.3 54.53,20.3 54.69,20.46 54.69,20.69 54.48,20.9 54.48,21.12 54.64,21.28 54.87,21.28 55.08,21.07 55.31,21.07 55.47,21.23 55.47,21.46 55.26,21.67 55.26,21.9 55.44,22.09 55.44,27.59 56.8,28.95 56.8,35.04 57.16,35.39 57.66,35.39 57.82,35.56 57.82,36.01 58.02,36.21 58.37,36.21 58.6,36.44 58.6,36.75 58.82,36.97 59.27,36.97 59.42,37.13 59.42,38.59 v3(59.82,38.99)
D1_MDQ54: length 47.6
  TOP w0.137: U18.J3 v2(45.9,11.71) ; v3(56.62,38.99) 57.02,39.39 U14.AD22
  BOTTOM w0.137: v3(56.62,38.99) 56.25,39.37 52.85,39.37 52.24,38.76 52.01,38.76 51.95,38.82 51.7,38.82 51.56,38.69 51.56,38.44 51.62,38.37 51.62,38.14 51.46,37.98 51.24,37.98 51.17,38.05 50.94,38.05 50.78,37.89 50.78,37.66 50.85,37.59 50.85,37.37 50.69,37.21 50.46,37.21 50.39,37.27 50.17,37.27 50.01,37.11 50.01,36.88 50.07,36.82 50.07,36.59 49.91,36.43 49.68,36.43 49.62,36.49 49.39,36.49 49.23,36.33 49.23,36.11 49.3,36.04 49.3,35.81 48.92,35.44 48.92,35.04 48.91,35.02 48.91,34.19 48.18,33.47 47.99,33.47 47.25,34.21 47,34.21 46.86,34.07 46.86,33.82 47.6,33.08 47.6,32.89 47.09,32.38 45.16,32.38 44.67,31.89 44.67,30.23 44.53,30.09 44.25,30.09 44.07,29.91 44.07,29.72 44.25,29.54 44.53,29.54 44.67,29.4 44.67,27.96 42.33,25.62 42.33,19.67 42.93,19.07 44.4,19.07 44.56,18.91 44.56,18.24 44.42,18.11 43.96,18.11 43.72,17.87 43.72,15.14 44.08,14.79 44.53,14.79 44.92,14.39 44.92,13.47 45.32,13.07 45.32,12.74 44.92,12.35 44.92,11.85 45.06,11.71 v2(45.9,11.71)
D1_MDQ55: length 47.7
  TOP w0.137: U14.AE22 56.22,39.39 v3(55.82,38.99) ; U18.J7 v2(47.48,11.71)
  BOTTOM w0.137: v2(47.48,11.71) 46.46,11.71 45.73,12.44 45.73,13.01 45.36,13.39 45.36,18.97 44.68,19.65 43.45,19.65 42.84,20.26 42.84,25.48 43.32,25.96 43.54,25.96 44.41,25.09 44.64,25.09 44.8,25.25 44.8,25.47 43.93,26.34 43.93,26.57 44.09,26.73 44.32,26.73 45.19,25.86 45.42,25.86 45.58,26.02 45.58,26.25 44.71,27.12 44.71,27.35 45.06,27.7 46.74,27.7 47.41,28.37 47.41,29 47.25,29.16 46.85,29.16 46.69,29.32 46.69,29.54 46.85,29.71 47.25,29.71 47.41,29.87 47.41,30.09 47.25,30.25 46.85,30.25 46.69,30.41 46.69,30.64 46.85,30.8 47.25,30.8 47.41,30.96 47.41,31.9 50.04,34.53 50.04,35.93 53.1,38.99 v3(55.82,38.99)
D1_MDQ56: length 48.3
  TOP w0.137: U14.AH25 53.45,37 53.38,36.92 52.74,36.92 50.6,34.79 50.6,32.2 51.34,31.46 51.34,23.63 51.2,23.49 50.67,23.49 50.53,23.63 50.53,24.13 50.37,24.29 49.68,24.29 49.52,24.45 49.52,24.68 49.68,24.84 50.37,24.84 50.53,25 50.53,25.23 50.37,25.39 49.68,25.39 49.52,25.55 49.52,25.78 49.68,25.94 50.37,25.94 50.53,26.1 50.53,26.32 50.37,26.49 49.68,26.49 49.52,26.65 49.52,26.87 49.68,27.03 50.37,27.03 50.53,27.2 v2(50.53,31.59) ; v2(49.91,19.58) 46.79,19.58 U18.A3
  L4_INT_2 w0.107: v2(49.91,19.58) 50.46,19.58 50.7,19.82 50.7,25.18 51.83,26.31 51.83,30.29 v2(50.53,31.59)
D1_MDQ57: length 48.3
  TOP w0.137: v2(51.95,31.31) 51.95,23.7 52.12,23.54 52.69,23.54 52.89,23.74 52.89,25.81 53.05,25.97 53.65,25.97 53.81,26.13 53.81,26.36 53.65,26.52 53.05,26.52 52.89,26.68 52.89,26.91 53.05,27.07 53.64,27.07 53.8,27.23 53.8,27.45 53.64,27.62 53.05,27.62 52.89,27.78 52.89,28 53.05,28.16 53.64,28.16 53.8,28.33 53.8,28.55 53.64,28.71 53.05,28.71 52.89,28.87 52.89,29.1 53.05,29.26 53.64,29.26 53.8,29.42 53.8,29.65 53.64,29.81 53.05,29.81 52.89,29.97 52.89,30.2 53.05,30.36 53.64,30.36 53.8,30.52 53.8,30.75 53.64,30.91 53.05,30.91 52.89,31.07 52.89,31.3 53.05,31.46 53.64,31.46 53.8,31.62 53.8,31.84 53.64,32 53.05,32 52.89,32.17 52.89,35.03 53.66,35.79 54.01,35.79 54.22,36.01 54.22,36.37 54.44,36.59 54.87,36.59 55.02,36.74 55.02,37.39 U14.AF24 ; U18.B8 v2(49.72,17.71)
  L4_INT_2 w0.107: v2(51.95,31.31) 52.24,31.02 52.24,26.14 51.12,25.01 51.12,19.65 50.12,18.66 50.12,18.11 v2(49.72,17.71)
D1_MDQ58: length 48.2
  TOP w0.137: v2(46.49,35.7) 46.19,36 46.19,36.28 46.43,36.51 46.43,36.81 45.88,37.35 45.88,39.69 47.04,40.85 52.89,40.85 53.04,40.7 53.46,40.7 53.54,40.62 53.98,40.62 54.22,40.38 54.22,39.97 54.62,39.57 U14.AG22 ; U18.C3 v2(44.92,16.91)
  L4_INT_2 w0.107: v2(44.92,16.91) 45.03,17.01 45.68,17.01 45.93,16.77 46.51,16.77 46.73,16.99 46.73,17.46 46.15,18.04 46.15,18.18 46.53,18.56 46.53,18.71 46.38,18.86 46.23,18.86 45.85,18.49 45.7,18.49 45.53,18.66 45.53,19.94 45.14,20.33 45.14,20.62 45.25,20.73 45.51,20.73 45.62,20.83 45.62,21.05 45.51,21.15 45.17,21.15 45.06,21.26 45.06,21.47 45.17,21.58 45.54,21.58 45.65,21.69 45.65,21.9 45.54,22.01 45.17,22.01 45.06,22.12 45.06,22.33 45.17,22.44 45.54,22.44 45.65,22.54 45.65,22.76 45.54,22.86 45.25,22.86 45.14,22.97 45.14,24.32 45.25,24.43 45.57,24.43 45.68,24.53 45.68,24.75 45.57,24.85 45.25,24.85 45.14,24.96 45.14,25.2 45.87,25.93 45.87,26.8 46.16,27.09 46.16,27.42 46.27,27.53 46.38,27.53 46.48,27.64 46.48,27.85 46.38,27.96 46.2,27.96 46.09,28.06 46.09,28.28 46.2,28.38 46.38,28.38 46.48,28.49 46.48,28.7 46.38,28.81 46.07,28.81 45.97,28.92 45.97,29.13 46.07,29.24 46.38,29.24 46.48,29.34 46.48,29.56 46.38,29.66 45.2,29.66 45.1,29.77 45.1,29.98 45.2,30.09 46.38,30.09 46.48,30.2 46.48,30.41 46.38,30.52 45.79,30.52 45.68,30.62 45.68,30.84 45.79,30.94 46.38,30.94 46.48,31.05 46.48,31.26 46.38,31.37 46.2,31.37 46.09,31.48 46.09,31.69 46.2,31.8 46.38,31.8 46.48,31.9 46.48,32.12 46.38,32.22 46.27,32.22 46.16,32.33 46.16,32.61 46.75,33.2 46.75,34.27 46.32,34.71 46.32,35.53 v2(46.49,35.7)
D1_MDQ59: length 48.2
  TOP w0.137: U14.AF22 55.42,39.39 55.03,38.99 54.39,38.99 54.23,39.16 54.23,39.54 54.22,39.54 54.22,39.56 54,39.79 53.36,39.79 53.35,39.8 53.08,39.8 52.84,40.03 52.84,40.27 52.71,40.41 47.7,40.41 46.92,39.63 46.92,38.74 46.98,38.69 46.98,35.5 46.49,35.02 45.38,35.02 45.22,35.18 45.22,36.39 45.06,36.56 44.83,36.56 44.67,36.39 44.67,35.18 44.51,35.02 44.2,35.02 43.93,34.74 43.93,33.68 44.07,33.55 v2(46.34,33.55) ; U18.C7 48.35,16.68 47.76,16.68 47.29,17.15 v2(46.35,17.15)
  L4_INT_2 w0.107: v2(46.35,17.15) 46.13,17.15 44.65,18.63 44.65,30.6 44.78,30.73 45.09,30.73 45.22,30.85 45.22,31.03 45.09,31.15 44.78,31.15 44.65,31.28 44.65,31.45 44.78,31.58 45.09,31.58 45.22,31.7 45.22,31.88 45.09,32.01 44.78,32.01 44.65,32.13 44.65,32.31 44.78,32.43 45.2,32.43 45.33,32.56 45.33,32.74 45.21,32.86 44.78,32.86 44.65,32.98 44.65,33.53 45.19,34.07 45.81,34.07 v2(46.34,33.55)
D1_MDQ60: length 48.4
  TOP w0.137: v2(52.39,32.73) 52.39,35.13 53.45,36.2 U14.AH26 ; U18.C2 v2(44.12,16.91)
  L4_INT_2 w0.107: v2(44.12,16.91) 43.71,17.32 41.49,17.32 40.9,16.73 40.9,11.36 41.46,10.8 41.46,10.04 41.72,9.78 42.33,9.78 42.53,9.98 42.53,11.08 42.74,11.29 48.32,11.29 49.23,12.2 50.37,12.2 50.47,12.31 50.47,12.32 50.91,12.75 50.91,13.35 51.32,13.76 51.32,16.68 52.03,17.39 52.03,24.55 53.27,25.8 53.27,25.95 53.28,25.96 53.28,31.86 53.07,32.08 53.07,32.52 52.85,32.73 v2(52.39,32.73)
D1_MDQ61: length 48.3
  TOP w0.137: U18.C8 v2(49.72,16.91) ; U14.AG25 54.36,37 53.92,36.56 53,36.56 51.05,34.6 v2(51.05,32.38)
  L4_INT_2 w0.107: v2(49.72,16.91) 50.1,16.52 50.1,15.95 49.88,15.72 49.6,15.72 48.62,14.75 47.86,14.75 47.86,14.74 47.7,14.74 47.54,14.58 47.54,14.2 47.78,13.95 47.78,13.49 47.49,13.2 46.3,13.2 46.02,13.49 46.02,14.58 45.82,14.78 45.57,14.78 45.32,14.53 45.32,13.65 45.06,13.38 44.36,13.38 44.1,13.13 44.1,12.42 44.43,12.1 44.85,12.1 44.97,12.22 44.97,12.38 45.1,12.5 45.27,12.5 45.4,12.38 45.4,12.22 45.52,12.1 48.66,12.1 49.3,12.75 49.3,12.75 50.1,13.55 50.1,13.94 50.99,14.83 50.99,18.33 51.62,18.96 51.62,24.72 52.86,25.97 52.86,31.44 51.92,32.38 v2(51.05,32.38)
D1_MDQ62: length 48.3
  TOP w0.137: U18.D3 v2(44.92,16.11) ; U14.AF23 55.42,38.59 55.02,38.19 53.52,38.19 53.23,37.9 52.46,37.9 49.57,35.02 49.57,34.71 48.55,33.68 48.55,32.52 48.39,32.36 47.98,32.36 47.82,32.19 47.82,31.97 47.98,31.81 48.39,31.81 48.55,31.65 48.55,31.42 48.39,31.26 47.98,31.26 47.82,31.1 47.82,30.87 47.98,30.71 48.39,30.71 48.55,30.55 48.55,30.32 48.39,30.16 47.98,30.16 47.82,30 47.82,29.77 47.98,29.61 48.39,29.61 48.55,29.45 48.55,27.97 48.74,27.77 49.49,27.77 49.67,27.96 49.67,31.36 49.16,31.87 49.16,32.94 v2(49.46,33.24)
  L4_INT_2 w0.107: v2(49.46,33.24) 49.46,31.26 50.42,30.3 50.42,27.22 49.09,25.88 49.09,19.35 48.58,18.84 48.58,16.42 48.01,15.85 47.25,15.85 47.14,15.96 47.14,16.28 47.03,16.38 46.82,16.38 46.71,16.28 46.71,15.96 46.61,15.85 46.35,15.85 46.09,16.11 v2(44.92,16.11)
D1_MDQ63: length 48.4
  TOP w0.137: U18.D7 47.97,16.26 v2(47.63,16.26) ; U14.AH22 53.15,39.4 53.03,39.51 52.13,39.51 51.73,39.92 49.15,39.92 47.48,38.25 47.48,35.22 47.84,34.87 47.84,33.37 47.7,33.24 47.06,33.24 46.92,33.37 v2(46.92,34.82)
  L4_INT_2 w0.107: v2(46.92,34.82) 47.47,34.27 47.47,34.06 47.57,33.95 47.84,33.95 47.95,33.85 47.95,33.63 47.84,33.53 47.57,33.53 47.47,33.42 47.47,32.22 47.36,32.12 47.04,32.12 46.93,32.01 46.93,31.8 47.04,31.69 47.49,31.69 47.6,31.58 47.6,31.37 47.49,31.26 47.04,31.26 46.93,31.16 46.93,30.94 47.04,30.84 47.36,30.84 47.47,30.73 47.47,29.91 47.36,29.8 47.04,29.8 46.93,29.69 46.93,29.48 47.04,29.37 47.43,29.37 47.54,29.27 47.54,29.05 47.43,28.95 47.04,28.95 46.93,28.84 46.93,28.63 47.04,28.52 47.43,28.52 47.54,28.41 47.54,28.2 47.43,28.09 47.04,28.09 46.93,27.98 46.93,27.77 47.04,27.66 47.36,27.66 47.47,27.56 47.47,27.08 46.75,26.36 46.75,26.15 46.64,26.04 46.44,26.04 46.33,25.94 46.33,25.72 46.44,25.62 46.77,25.62 46.87,25.51 46.87,24.98 46.77,24.87 46.22,24.87 46.11,24.76 46.11,24.55 46.22,24.44 46.64,24.44 46.75,24.34 46.75,24.12 46.64,24.02 46.17,24.02 46.07,23.91 46.07,23.7 46.17,23.59 46.64,23.59 46.75,23.48 46.75,23.27 46.64,23.16 46.19,23.16 46.09,23.06 46.09,22.84 46.19,22.74 46.64,22.74 46.75,22.63 46.75,22.42 46.64,22.31 46.19,22.31 46.09,22.2 46.09,21.99 46.19,21.88 46.64,21.88 46.75,21.78 46.75,21.13 46.64,21.03 46.19,21.03 46.09,20.92 46.09,20.71 46.19,20.6 46.64,20.6 46.75,20.49 46.75,20.28 46.64,20.17 46.1,20.17 46,20.07 46,19.85 46.1,19.75 46.64,19.75 46.75,19.64 46.75,18.9 46.86,18.8 47,18.8 47.1,18.69 47.1,18.44 46.93,18.26 46.93,17.64 47.14,17.43 47.14,16.75 v2(47.63,16.26)
D1_MDQS0_N: length 45.7
  TOP w0.124: U14.A24 75.71,37.5 80.22,37.5 83.07,34.66 83.07,33.72 v2(83.33,33.46)
  TOP w0.137: v2(92.44,14.46) 91.87,13.89 91.46,13.89 U15.F3
  L4_INT_2 w0.094: v2(92.44,14.46) 92.44,15.03 92.79,15.38 92.79,15.89 92.59,16.09 92.59,18.51 92.24,18.86 92.24,24.34 91.67,24.91 91.16,24.91 90.6,24.35 90.48,24.35 90.29,24.53 90.29,24.71 90.83,25.25 90.83,25.74 89.75,26.81 89.12,26.81 88.78,26.47 88.35,26.47 87.37,27.46 87.37,27.65 88.11,28.4 88.11,28.84 87.76,29.19 87.18,29.19 86.33,28.33 86.11,28.33 85.97,28.47 85.97,28.64 87,29.66 87,30.13 86.65,30.48 86.09,30.48 85.32,29.7 85.12,29.7 84.99,29.84 84.99,30.03 85.45,30.49 85.45,30.93 85.03,31.35 84.59,31.35 84.13,30.89 83.93,30.89 83.69,31.13 83.69,31.62 83.01,32.3 83.01,33.14 v2(83.33,33.46)
D1_MDQS0_P: length 45.8
  TOP w0.124: U14.A25 75.61,37.18 80.09,37.18 82.7,34.58 82.7,33.73 v2(82.37,33.4)
  TOP w0.137: U15.G3 91.43,13.5 92.23,13.5 92.42,13.69 v2(92.44,13.69)
  L4_INT_2 w0.094: v2(92.44,13.69) 92.44,13.86 91.98,14.32 91.98,15.1 92.28,15.39 92.28,15.87 92.22,15.94 92.22,18.36 91.87,18.71 91.87,24.18 91.51,24.54 91.32,24.54 90.75,23.98 90.32,23.98 89.92,24.38 89.92,24.86 90.46,25.4 90.46,25.58 89.6,26.44 89.27,26.44 88.93,26.1 88.2,26.1 87,27.3 87,27.81 87.74,28.55 87.74,28.68 87.61,28.81 87.34,28.81 86.48,27.96 85.96,27.96 85.6,28.32 85.6,28.79 86.62,29.82 86.62,29.98 86.49,30.11 86.25,30.11 85.47,29.33 84.97,29.33 84.61,29.68 84.61,30.19 85.08,30.65 85.08,30.78 84.88,30.98 84.74,30.98 84.28,30.52 83.78,30.52 83.32,30.98 83.32,31.46 82.59,32.2 82.59,33.18 v2(82.37,33.4)
D1_MDQS1_N: length 48.8
  TOP w0.137: v2(93.77,18.12) 93.99,18.34 94.3,18.34 94.44,18.2 U15.A7 ; v3(73.42,39) U14.C23
  BOTTOM w0.124: v3(73.42,39) 73.57,38.85 73.63,38.85 73.68,38.9 75.19,38.9 77.53,36.56 77.53,36.07 77.22,35.76 76.74,35.76 76.62,35.64 76.62,35.48 76.74,35.37 76.95,35.37 77.26,35.05 77.26,33.25 77.6,32.92 77.6,31.97 77.72,31.85 77.9,31.85 78.45,32.4 78.95,32.4 79.27,32.08 79.27,31.61 78.65,30.99 78.65,30.77 78.81,30.62 79.03,30.62 79.63,31.21 80.12,31.21 80.43,30.9 80.43,30.41 79.83,29.81 79.83,29.59 79.97,29.46 80.21,29.46 80.8,30.05 81.3,30.05 81.63,29.72 81.63,29.24 81.02,28.63 81.02,28.37 81.14,28.25 81.39,28.25 82.57,29.42 83.01,29.42 83.49,28.94 83.49,28.49 82.3,27.3 82.3,27.12 82.6,26.82 83.04,26.82 84.27,28.06 86.62,28.06 87.04,27.64 87.04,27.2 86.68,26.84 86.68,26.66 86.86,26.48 87.03,26.48 87.39,26.85 87.83,26.85 88.35,26.33 88.35,25.25 92.22,21.38 92.22,19.29 93.5,18.01 93.65,18.01 v2(93.77,18.12)
D1_MDQS1_P: length 48.8
  TOP w0.137: v3(73.42,38.2) U14.D23 ; v2(93.77,17.34) 93.8,17.31 U15.B7
  BOTTOM w0.124: v3(73.42,38.2) 73.74,38.51 73.81,38.58 75.06,38.58 77.21,36.43 77.21,36.2 77.09,36.08 76.6,36.08 76.3,35.78 76.3,35.35 76.6,35.05 76.82,35.05 76.94,34.92 76.94,33.11 77.28,32.78 77.28,31.84 77.59,31.53 78.03,31.53 78.58,32.08 78.82,32.08 78.95,31.95 78.95,31.74 78.33,31.13 78.33,30.64 78.68,30.3 79.16,30.3 79.76,30.89 79.99,30.89 80.11,30.77 80.11,30.54 79.51,29.94 79.51,29.46 79.83,29.14 80.34,29.14 80.44,29.23 80.94,29.73 81.17,29.73 81.31,29.59 81.31,29.38 80.7,28.76 80.7,28.24 81.01,27.93 81.53,27.93 82.7,29.1 82.87,29.1 83.17,28.8 83.17,28.63 81.98,27.43 81.98,26.99 82.47,26.5 83.17,26.5 84.4,27.74 86.49,27.74 86.72,27.51 86.72,27.33 86.36,26.97 86.36,26.53 86.72,26.16 87.16,26.16 87.53,26.53 87.7,26.53 88.03,26.2 88.03,25.12 91.9,21.25 91.9,19.08 93.65,17.34 v2(93.77,17.34)
D1_MDQS2_N: length 49.2
  TOP w0.124: v3(71.83,35.79) 71.83,35.79 U14.F26
  TOP w0.137: v2(80.37,14.42) 80.85,14.9 81.44,14.9 81.59,14.74 81.59,14.48 81.45,14.35 80.91,14.35 80.43,13.87 80,13.87 U16.F3
  L4_INT_2 w0.094: v2(80.37,14.42) 80.37,14.42 80.37,14.43 80.9,14.96 81.57,14.96 82.52,15.91 82.52,16.57 81.97,17.12 81.63,17.12 81.54,17.21 81.54,18.18 82.97,19.61 82.97,20.52 82.69,20.8 82.69,20.93 82.93,21.17 82.93,21.61 82.44,22.09 82,22.09 81.77,21.85 81.63,21.85 81.38,22.11 81.38,22.24 81.69,22.55 81.69,22.99 81.2,23.48 80.76,23.48 80.32,23.03 80.19,23.03 79.56,23.66 79.56,23.8 80.58,24.81 80.58,25.25 80.09,25.74 79.65,25.74 78.64,24.72 78.5,24.72 77.93,25.29 77.93,25.43 78.91,26.41 78.91,26.85 78.43,27.33 77.99,27.33 77.34,26.68 77.21,26.68 76.94,26.95 76.94,27.08 77.59,27.73 77.59,28.24 77.17,28.66 76.67,28.66 76.02,28.01 75.88,28.01 75.11,28.78 74.82,28.78 74.47,29.13 74.47,30.01 74.61,30.15 75.49,30.15 75.85,30.51 75.85,31.01 75.49,31.36 74.61,31.36 74.47,31.5 74.47,31.7 74.61,31.83 75.49,31.83 75.85,32.19 75.85,32.69 75.49,33.05 74.61,33.05 74.47,33.18 74.47,33.4 73.86,34.02 73.27,34.02 72.67,34.62 71.55,34.62 71.45,34.73 71.45,35.16 71.83,35.54 v3(71.83,35.79)
D1_MDQS2_P: length 49.1
  TOP w0.124: U14.F25 v3(71.83,36.59)
  TOP w0.137: U16.G3 79.93,13.48 80.6,13.48 v2(81.06,13.93)
  L4_INT_2 w0.094: v2(81.06,13.93) 80.92,14.08 80.56,14.08 80.53,14.05 80.22,14.05 80,14.27 80,14.58 80.75,15.33 81.42,15.33 82.15,16.07 82.15,16.41 81.82,16.75 81.48,16.75 81.17,17.06 81.17,18.33 82.6,19.77 82.6,20.36 82.32,20.64 82.32,21.08 82.56,21.32 82.56,21.46 82.29,21.72 82.16,21.72 81.92,21.48 81.48,21.48 81.01,21.96 81.01,22.4 81.32,22.71 81.32,22.84 81.05,23.1 80.92,23.1 80.48,22.66 80.04,22.66 79.19,23.51 79.19,23.95 80.2,24.96 80.2,25.1 79.94,25.36 79.81,25.36 78.79,24.35 78.35,24.35 77.56,25.14 77.56,25.58 78.54,26.56 78.54,26.7 78.28,26.96 78.14,26.96 77.49,26.31 77.05,26.31 76.57,26.8 76.57,27.24 77.22,27.89 77.22,28.08 77.02,28.29 76.82,28.29 76.17,27.64 75.73,27.64 74.96,28.4 74.67,28.4 74.1,28.97 74.1,30.17 74.46,30.52 75.34,30.52 75.48,30.66 75.48,30.86 75.34,30.99 74.46,30.99 74.1,31.35 74.1,31.85 74.46,32.2 75.34,32.2 75.48,32.34 75.48,32.54 75.34,32.67 74.46,32.67 74.1,33.03 74.1,33.25 73.71,33.65 73.07,33.65 72.48,34.24 71.39,34.24 71.08,34.55 71.08,35.32 71.4,35.64 71.4,36.17 v3(71.83,36.59)
D1_MDQS3_N: length 46.5
  TOP w0.124: 68.23,36.99 U14.K25 ; 82.59,18.11 v2(82.29,18.4)
  TOP w0.137: 68.23,36.99 v3(68.63,36.59) ; U16.A7 82.59,18.11
  BOTTOM w0.124: v2(82.29,18.4) 82.31,18.42 82.31,18.8 82.11,19 82.11,20.38 81.88,20.61 81.58,20.61 81.46,20.48 81.46,19.36 81.14,19.04 80.46,19.04 80.07,19.43 80.07,20.41 78.88,21.59 78.7,21.59 77.82,20.71 77.09,20.71 76.81,21 76.81,21.48 77.6,22.28 77.6,22.87 77.3,23.17 76.41,23.17 76.22,22.99 76.22,21.23 75.91,20.91 75.17,20.91 74.58,21.5 74.58,24.52 74.34,24.76 73.7,24.76 73.57,24.63 73.57,22.1 73.21,21.74 72.4,21.74 71.96,22.17 71.96,25.03 71.84,25.15 71.24,25.15 70.93,25.47 70.93,26.23 71.24,26.54 71.87,26.54 71.99,26.66 71.99,27.04 68.47,30.56 68.47,33.95 67.86,34.57 67.86,35.25 68.22,35.61 68.22,35.9 68.26,35.93 68.26,35.95 68.63,36.31 v3(68.63,36.59)
D1_MDQS3_P: length 46.5
  TOP w0.124: U14.K26 68.23,36.19
  TOP w0.137: 68.23,36.19 v3(68.63,35.79) ; v2(82.29,17.6) 82.58,17.31 U16.B7
  BOTTOM w0.124: v3(68.63,35.79) 68.63,35.56 68.18,35.12 68.18,34.7 68.79,34.09 68.79,30.69 72.31,27.17 72.31,26.53 72,26.22 71.38,26.22 71.25,26.1 71.25,25.6 71.38,25.47 71.97,25.47 72.28,25.16 72.28,22.31 72.53,22.06 73.08,22.06 73.25,22.24 73.25,24.76 73.57,25.08 74.48,25.08 74.9,24.65 74.9,21.63 75.3,21.23 75.78,21.23 75.9,21.36 75.9,23.12 76.27,23.49 77.43,23.49 77.92,23.01 77.92,22.15 77.13,21.35 77.13,21.13 77.23,21.03 77.69,21.03 78.57,21.91 79.01,21.91 80.39,20.54 80.39,19.57 80.59,19.36 81.01,19.36 81.14,19.49 81.14,20.62 81.45,20.93 82.01,20.93 82.43,20.51 82.43,19.14 82.68,18.88 82.68,17.99 v2(82.29,17.6)
D1_MDQS4_N: length 47
  TOP w0.124: v3(60.62,36.59) 61.02,36.99 U14.W25
  TOP w0.137: U17.F3 v2(58.06,15.37)
  BOTTOM w0.124: v2(58.06,15.37) 58.28,15.15 58.75,15.15 59.1,15.5 59.1,19.52 59.52,19.93 60.89,19.93 61.07,20.11 61.07,20.63 60.88,20.83 58.94,20.83 58.62,21.16 58.62,21.82 58.9,22.11 60.3,22.11 60.46,22.27 60.46,22.75 60.28,22.94 58.4,22.94 58.1,23.24 58.1,23.94 58.36,24.2 60.28,24.2 60.46,24.38 60.46,24.64 60.28,24.82 58.56,24.82 58.18,25.2 58.18,25.73 58.54,26.08 60.39,26.08 60.66,26.35 60.66,26.65 60.42,26.9 59.34,26.9 58.9,27.34 58.9,27.92 59.34,28.37 60.47,28.37 60.76,28.66 60.76,29.03 60.56,29.23 59.19,29.23 58.9,29.52 58.9,30.22 59.18,30.5 60.29,30.5 60.46,30.67 60.46,30.96 60.32,31.09 59.31,31.09 58.95,31.46 58.95,31.98 59.31,32.35 60.32,32.35 60.46,32.49 60.46,32.68 59.91,33.23 59.91,35.32 60.22,35.63 60.22,35.65 60.26,35.69 60.26,35.95 60.62,36.31 v3(60.62,36.59)
D1_MDQS4_P: length 47.1
  TOP w0.124: U14.W26 60.62,35.8 v3(60.62,35.79)
  TOP w0.137: U17.G3 57.09,13.6 57.32,13.6 57.4,13.52 57.63,13.52 57.8,13.69 57.8,13.92 57.72,14 57.72,14.23 v2(58.06,14.57)
  BOTTOM w0.124: v3(60.62,35.79) 60.58,35.75 60.58,35.55 60.54,35.51 60.54,35.5 60.23,35.19 60.23,33.36 60.78,32.81 60.78,32.35 60.46,32.03 59.45,32.03 59.27,31.85 59.27,31.59 59.45,31.41 60.46,31.41 60.78,31.09 60.78,30.54 60.42,30.18 59.31,30.18 59.22,30.09 59.22,29.65 59.32,29.55 60.69,29.55 61.08,29.16 61.08,28.53 60.6,28.05 59.47,28.05 59.22,27.79 59.22,27.47 59.47,27.22 60.55,27.22 60.98,26.79 60.98,26.22 60.52,25.76 58.67,25.76 58.5,25.59 58.5,25.34 58.69,25.14 60.41,25.14 60.78,24.77 60.78,24.25 60.41,23.88 58.49,23.88 58.42,23.81 58.42,23.37 58.53,23.26 60.41,23.26 60.78,22.89 60.78,22.14 60.44,21.79 59.03,21.79 58.94,21.69 58.94,21.29 59.08,21.15 61.01,21.15 61.39,20.77 61.39,19.98 61.02,19.61 59.65,19.61 59.42,19.38 59.42,15.36 58.89,14.83 58.32,14.83 v2(58.06,14.57)
D1_MDQS5_N: length 46.8
  TOP w0.124: v2(60.4,18.51) 60.84,18.95 60.84,19.11 60.74,19.21 60.5,19.21 60.12,18.83 60.1,18.83 60,18.72 U17.A7
  TOP w0.137: U14.AC26 v3(57.42,35.8)
  L4_INT_2 w0.094: v2(60.4,18.51) 60.4,18.52 60.33,18.59 60.33,19.38 60.01,19.7 60.01,20.45 59.24,21.22 59.24,21.9 60.82,23.48 60.82,23.67 60.66,23.84 60.51,23.84 58.8,22.12 58.37,22.12 58.01,22.48 58.01,23.04 59.63,24.67 59.63,24.86 59.47,25.03 59.32,25.03 57.42,23.13 56.94,23.13 56.53,23.54 56.53,24.14 56.88,24.49 56.88,25.82 57.23,26.18 59.32,26.18 59.43,26.29 59.43,26.51 59.29,26.65 57.23,26.65 56.88,27 56.88,27.5 57.23,27.86 59.28,27.86 59.43,28 59.43,28.22 59.32,28.33 57.23,28.33 56.88,28.68 56.88,29.18 57.23,29.54 59.32,29.54 59.43,29.64 59.43,29.84 59.26,30.01 57.23,30.01 56.88,30.36 56.88,31.06 57.57,31.75 57.57,33.09 57.82,33.34 57.82,35.14 57.42,35.54 v3(57.42,35.8)
D1_MDQS5_P: length 46.8
  TOP w0.137: v3(57.42,36.6) U14.AC25 ; U17.B7 v2(60.4,17.71)
  L4_INT_2 w0.094: v3(57.42,36.6) 57.85,36.17 57.85,35.64 58.19,35.3 58.19,33.19 57.94,32.93 57.94,31.59 57.25,30.9 57.25,30.52 57.39,30.38 59.41,30.38 59.8,30 59.8,29.49 59.48,29.17 57.39,29.17 57.25,29.03 57.25,28.84 57.39,28.7 59.47,28.7 59.8,28.37 59.8,27.85 59.44,27.49 57.39,27.49 57.25,27.35 57.25,27.15 57.39,27.02 59.45,27.02 59.8,26.67 59.8,26.13 59.47,25.81 57.39,25.81 57.25,25.67 57.25,24.33 56.9,23.98 56.9,23.69 57.09,23.5 57.27,23.5 59.17,25.4 59.62,25.4 60,25.02 60,24.52 58.38,22.89 58.38,22.64 58.52,22.49 58.65,22.49 60.36,24.21 60.81,24.21 61.19,23.83 61.19,23.33 59.61,21.75 59.61,21.37 60.38,20.61 60.38,19.85 60.7,19.53 60.7,18.74 60.78,18.66 60.78,18.66 60.79,18.64 60.79,18.1 v2(60.4,17.71)
D1_MDQS6_N: length 47.7
  TOP w0.137: v2(46.84,14.17) 46.59,14.17 46.53,14.11 U18.F3 ; v3(56.62,38.19) 57.02,38.59 U14.AD23
  BOTTOM w0.124: v3(56.62,38.19) 56.5,38.06 56.38,38.06 56.37,38.06 56.35,38.06 56.12,37.83 55.67,37.83 55.63,37.87 54.12,37.87 51.84,35.59 51.84,35.21 51.81,35.18 51.81,33.33 51.84,33.3 51.84,31.84 51.53,31.53 51.53,30.23 51.16,29.86 49.21,29.86 49.02,29.67 49.02,29.41 49.19,29.24 51.16,29.24 51.53,28.87 51.53,27.88 51.85,27.57 51.85,27.15 51.5,26.8 51.03,26.8 49.77,28.06 49.55,28.06 49.39,27.9 49.39,27.71 50.67,26.43 50.67,25.98 50.31,25.61 49.85,25.61 49.48,25.99 49.3,25.99 46.83,23.51 45.51,23.51 45.33,23.33 45.33,23.07 45.51,22.89 46.83,22.89 47.2,22.52 47.2,21.83 46.83,21.46 45.39,21.46 45.2,21.27 45.2,21.01 45.37,20.84 46.83,20.84 47.2,20.47 47.2,15.2 46.86,14.87 46.86,14.42 46.85,14.4 46.85,14.17 v2(46.84,14.17)
D1_MDQS6_P: length 47.7
  TOP w0.137: v3(55.82,38.19) 56.22,38.59 U14.AE23 ; v2(46.4,13.65) 46.33,13.71 45.49,13.71 45.32,13.54 U18.G3
  BOTTOM w0.124: v3(55.82,38.19) 53.99,38.19 51.52,35.73 51.52,35.34 51.49,35.31 51.49,33.19 51.52,33.17 51.52,31.97 51.21,31.66 51.21,30.36 51.03,30.18 49.08,30.18 48.7,29.8 48.7,29.28 49.06,28.92 51.03,28.92 51.21,28.73 51.21,27.75 51.53,27.43 51.53,27.29 51.37,27.12 51.16,27.12 49.9,28.38 49.42,28.38 49.07,28.04 49.07,27.57 50.35,26.29 50.35,26.11 50.18,25.93 49.98,25.93 49.61,26.31 49.17,26.31 46.69,23.83 45.38,23.83 45.01,23.46 45.01,22.94 45.38,22.57 46.69,22.57 46.88,22.39 46.88,21.96 46.69,21.78 45.26,21.78 44.88,21.4 44.88,20.88 45.24,20.52 46.69,20.52 46.88,20.33 46.88,15.34 46.54,15 46.54,14.55 46.4,14.41 v2(46.4,13.65)
D1_MDQS7_N: length 48.2
  TOP w0.124: U14.AG23 54.4,38.6 53.99,39 53.47,39 53.47,39 53.19,39 53.19,39 52,39 51.8,38.8 51.51,38.8 50.91,39.4 50.5,39.4 50.02,38.93 50.02,38.5 50.75,37.78 50.75,37.59 50.44,37.27 50.3,37.27 49.13,38.45 48.51,38.45 48.14,38.08 48.14,37.55 49.21,36.48 49.21,36.2 48.63,35.63 48.63,35.48 48.5,35.34 v2(48.5,35.21)
  TOP w0.137: v2(47.94,18.11) 47.94,18.11 U18.A7
  L4_INT_2 w0.094: v2(48.5,35.21) 48.52,35.19 48.79,35.19 48.89,35.28 48.89,37.13 49.27,37.5 49.83,37.5 50.23,37.11 50.23,34.29 49.78,33.85 49.21,33.85 48.86,33.49 48.86,33.17 48.44,32.76 48.44,32.48 48.86,32.07 48.86,31.48 48.44,31.07 48.44,30.36 48.58,30.22 49.51,30.22 49.82,29.91 49.82,29.32 49.51,29.01 48.58,29.01 48.44,28.87 48.44,28.67 48.58,28.54 49.51,28.54 49.82,28.23 49.82,27.63 49.51,27.33 48.58,27.33 48.44,27.19 48.44,26.67 47.73,25.95 47.73,25.57 47.86,25.43 48.12,25.43 48.48,25.08 48.48,24.58 48.12,24.22 47.74,24.22 47.62,24.11 47.62,23.86 47.74,23.75 48.12,23.75 48.48,23.4 48.48,22.89 48.12,22.54 47.69,22.54 47.62,22.48 47.62,22.13 47.69,22.07 48.17,22.07 48.48,21.77 48.48,21.16 48.17,20.86 47.74,20.86 47.62,20.74 47.62,20.5 47.74,20.39 48.15,20.39 48.48,20.06 48.48,19.51 48.15,19.18 47.86,19.18 47.73,19.04 47.73,18.69 47.94,18.48 v2(47.94,18.11)
D1_MDQS7_P: length 48.3
  TOP w0.124: v2(48.45,34.5) 48.92,34.98 48.92,35.29 48.97,35.33 48.97,35.5 49.53,36.06 49.53,36.62 48.46,37.68 48.46,37.93 48.65,38.12 49.01,38.12 50.18,36.94 50.58,36.94 51.04,37.41 51.04,37.43 51.07,37.46 51.07,37.91 50.35,38.63 50.35,38.8 50.62,39.06 50.79,39.06 51.38,38.47 51.94,38.47 52.14,38.67 53.33,38.67 53.33,38.67 53.4,38.6 U14.AH23
  TOP w0.137: v2(47.96,17.18) 48.08,17.31 U18.B7
  L4_INT_2 w0.094: v2(48.45,34.5) 48.77,34.82 48.95,34.82 49.26,35.13 49.26,36.97 49.42,37.13 49.67,37.13 49.86,36.95 49.86,34.45 49.63,34.22 49.06,34.22 48.49,33.65 48.49,33.33 48.07,32.92 48.07,32.32 48.49,31.91 48.49,31.64 48.07,31.22 48.07,30.2 48.43,29.85 49.35,29.85 49.45,29.76 49.45,29.47 49.35,29.38 48.43,29.38 48.07,29.02 48.07,28.52 48.43,28.17 49.35,28.17 49.45,28.07 49.45,27.79 49.35,27.7 48.43,27.7 48.07,27.34 48.07,26.82 47.36,26.11 47.36,25.42 47.71,25.06 47.97,25.06 48.11,24.92 48.11,24.73 47.97,24.59 47.58,24.59 47.25,24.26 47.25,23.71 47.58,23.38 47.97,23.38 48.11,23.24 48.11,23.05 47.97,22.91 47.53,22.91 47.25,22.63 47.25,21.98 47.53,21.7 48.02,21.7 48.11,21.61 48.11,21.32 48.02,21.23 47.58,21.23 47.25,20.9 47.25,20.35 47.58,20.02 47.99,20.02 48.11,19.9 48.11,19.66 47.99,19.55 47.71,19.55 47.36,19.19 47.36,17.78 v2(47.96,17.18)
D1_MDQS8_N: length 49.2
  TOP w0.124: U565.F3 68.51,13.88 69.49,13.88 69.61,14 69.61,15.29 69.45,15.46 69.09,15.46 68.95,15.32 68.95,14.71 v2(68.99,14.67) ; v3(65.43,35.8) 65.03,36.2 U14.P26
  L4_INT_2 w0.094: v3(65.43,35.8) 64.94,35.31 64.94,32.66 65.11,32.49 65.11,32.49 65.24,32.35 65.24,31.03 65.73,30.54 65.73,29.91 65.83,29.82 67.57,29.82 68.15,29.24 68.15,28.69 67.81,28.35 66.56,28.35 66.47,28.26 66.47,27.11 66.56,27.02 67.6,27.02 67.95,26.67 67.95,25.84 67.63,25.53 66.62,25.53 66.53,25.43 66.53,24.94 66.62,24.84 68.3,24.84 68.61,24.53 68.61,23.85 68.3,23.54 66.75,23.54 66.66,23.44 66.66,22.93 66.75,22.83 68.93,22.83 69.24,22.52 69.24,21.84 68.93,21.53 66.67,21.53 66.58,21.43 66.58,21.06 66.67,20.96 68.93,20.96 69.24,20.65 69.24,19.97 68.93,19.66 68,19.66 67.73,19.39 67.73,18.91 68.02,18.63 69.61,18.63 70.08,18.15 70.08,17.31 69.64,16.87 68.35,16.87 67.9,16.42 67.9,15.73 68.12,15.51 68.26,15.51 68.52,15.78 68.72,15.78 68.86,15.63 68.86,15.45 68.59,15.18 68.59,15.05 68.97,14.67 v2(68.99,14.67)
D1_MDQS8_P: length 49.1
  TOP w0.124: U565.G3 68.53,13.56 69.84,13.56 70.01,13.73 v2(70.01,14.36) ; U14.P25 65.03,37 v3(65.43,36.6)
  L4_INT_2 w0.094: v2(70.01,14.36) 69.43,14.36 69.37,14.3 68.84,14.3 68.83,14.3 68.81,14.3 67.53,15.58 67.53,16.57 68.2,17.24 69.49,17.24 69.71,17.46 69.71,17.93 69.39,18.26 67.87,18.26 67.36,18.76 67.36,19.54 67.85,20.03 68.78,20.03 68.87,20.12 68.87,20.5 68.78,20.59 66.52,20.59 66.21,20.9 66.21,21.59 66.52,21.9 68.78,21.9 68.87,21.99 68.87,22.37 68.78,22.46 66.6,22.46 66.28,22.77 66.28,23.6 66.6,23.91 68.14,23.91 68.24,24 68.24,24.38 68.14,24.47 66.47,24.47 66.16,24.78 66.16,25.59 66.47,25.9 67.48,25.9 67.57,25.99 67.57,26.52 67.45,26.65 66.41,26.65 66.1,26.96 66.1,28.41 66.41,28.72 67.65,28.72 67.78,28.85 67.78,29.09 67.42,29.45 65.67,29.45 65.36,29.76 65.36,30.38 64.87,30.87 64.87,32.2 64.74,32.33 64.74,32.34 64.57,32.51 64.57,35.74 v3(65.43,36.6)
